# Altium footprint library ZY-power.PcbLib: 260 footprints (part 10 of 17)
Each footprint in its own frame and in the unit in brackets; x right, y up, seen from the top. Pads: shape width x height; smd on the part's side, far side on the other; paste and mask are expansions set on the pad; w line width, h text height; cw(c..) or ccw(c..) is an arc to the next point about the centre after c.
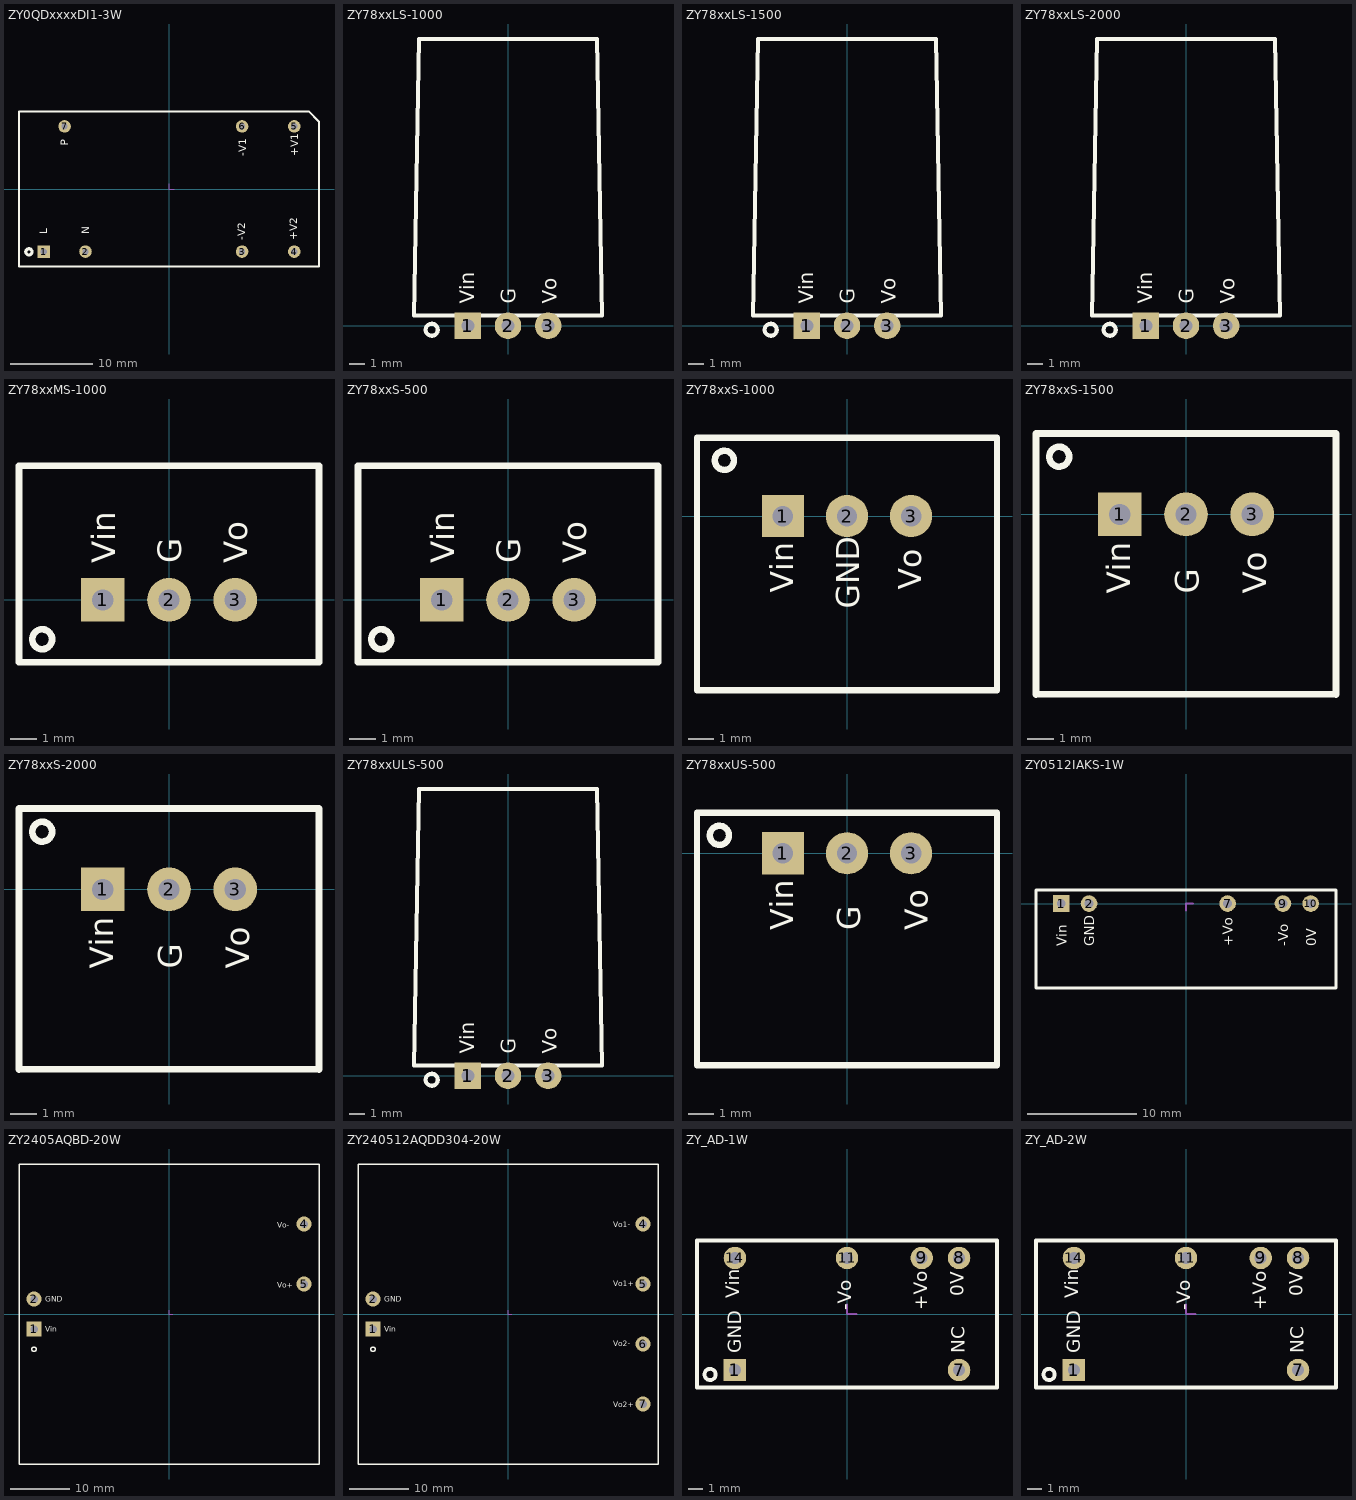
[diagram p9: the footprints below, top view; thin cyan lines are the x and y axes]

## ZY0QDxxxxDI1-3W [mil]
height 677.17
pads (7):
  rect 60x60 hole 30: 1(-600,-300)
  round 60 hole 30: 2(-400,-300) 3(350,-300) 4(600,-300) 5(600,300) 6(350,300) 7(-500,300)
Top Overlay:
  circle w15: c-671,-301 r15
  lines w10: -718.5,-372.05 718.5,-372.05 718.5,322.05 668.5,372.05 -718.5,372.05 -718.5,-372.05
  text "-V1" at 370,158 h36
  text "+V1" at 618,158 h36
  text "+V2" at 614,-245 h36
  text "-V2" at 366,-245 h36
  text "N" at -382,-216 h36
  text "L" at -583,-216 h36
  text "P" at -483,208 h36
Mechanical 15:
  lines w5: 0,25 0,0 25,0

## ZY78xxLS-1000 [mil]
height 393.7
pads (3):
  rect 66x66 hole 32: 1(-100,0)
  round 66 hole 32: 2(0,0) 3(100,0)
Top Overlay:
  circle w10: c-190,-10 r15
  lines w10: -234.25,25.35 -222.24,714.32 222.24,714.32 234.25,25.35 -234.25,25.35
  text "Vin" at -84,55 h36
  text "G" at 19,55 h36
  text "Vo" at 121,55 h36

## ZY78xxLS-1500 [mil]
height 393.7
pads (3):
  rect 66x66 hole 32: 1(-100,0)
  round 66 hole 32: 2(0,0) 3(100,0)
Top Overlay:
  circle w10: c-190,-10 r15
  lines w10: -234.25,25.35 -222.24,714.32 222.24,714.32 234.25,25.35 -234.25,25.35
  text "Vin" at -84,55 h36
  text "G" at 19,55 h36
  text "Vo" at 121,55 h36

## ZY78xxLS-2000 [mil]
height 393.7
pads (3):
  rect 66x66 hole 32: 1(-100,0)
  round 66 hole 32: 2(0,0) 3(100,0)
Top Overlay:
  circle w10: c-190,-10 r15
  lines w10: -234.25,25.35 -222.24,714.32 222.24,714.32 234.25,25.35 -234.25,25.35
  text "Vin" at -84,55 h36
  text "G" at 19,55 h36
  text "Vo" at 121,55 h36

## ZY78xxMS-1000 [mil]
height 401.57
pads (3):
  rect 66x66 hole 32: 1(-100,0)
  round 66 hole 32: 2(0,0) 3(100,0)
Top Overlay:
  circle w10: c-191.5,-59.49 r15
  lines w10: -226.5,-94.49 -226.5,202.76 226.5,202.76 226.5,-94.49 -226.5,-94.49
  text "Vin" at -81.5,55 h36
  text "G" at 18.5,55 h36
  text "Vo" at 118.5,55 h36

## ZY78xxS-500 [mil]
pads (3):
  rect 66x66 hole 32: 1(-100,0)
  round 66 hole 32: 2(0,0) 3(100,0)
Top Overlay:
  circle w10: c-191.5,-59.49 r15
  lines w10: -226.5,-94.49 -226.5,202.76 226.5,202.76 226.5,-94.49 -226.5,-94.49
  text "Vin" at -81.5,55 h36
  text "G" at 18.5,55 h36
  text "Vo" at 118.5,55 h36

## ZY78xxS-1000 [mil]
height 688.98
pads (3):
  rect 66x66 hole 32: 1(-100,0)
  round 66 hole 32: 2(0,0) 3(100,0)
Top Overlay:
  circle w10: c-191.5,87.05 r15
  lines w10: -234.25,-271.65 -234.25,122.05 234.25,122.05 234.25,-271.65 -234.25,-271.65
  text "Vin" at -84,-120 h36
  text "GND" at 19,-145 h36
  text "Vo" at 116,-115 h36

## ZY78xxS-1500 [mil]
height 688.98
pads (3):
  rect 66x66 hole 32: 1(-100,0)
  round 66 hole 32: 2(0,0) 3(100,0)
Top Overlay:
  circle w10: c-191.5,87.05 r15
  lines w10: -226.5,-271.95 -226.5,122.05 226.5,122.05 226.5,-271.95 ; -226.5,-271.65 226.5,-271.65
  text "Vin" at -84,-120 h36
  text "G" at 19,-120 h36
  text "Vo" at 121,-120 h36

## ZY78xxS-2000 [mil]
height 688.98
pads (3):
  rect 66x66 hole 32: 1(-100,0)
  round 66 hole 32: 2(0,0) 3(100,0)
Top Overlay:
  circle w10: c-191.5,87.05 r15
  lines w10: -226.5,-271.95 -226.5,122.05 226.5,122.05 226.5,-271.95 ; -226.5,-271.65 226.5,-271.65
  text "Vin" at -84,-120 h36
  text "G" at 19,-120 h36
  text "Vo" at 121,-120 h36

## ZY78xxULS-500 [mil]
height 393.7
pads (3):
  rect 66x66 hole 32: 1(-100,0)
  round 66 hole 32: 2(0,0) 3(100,0)
Top Overlay:
  circle w10: c-190,-10 r15
  lines w10: -234.25,25.35 -222.24,714.32 222.24,714.32 234.25,25.35 -234.25,25.35
  text "Vin" at -84,55 h36
  text "G" at 19,55 h36
  text "Vo" at 121,55 h36

## ZY78xxUS-500 [mil]
height 688.98
pads (3):
  rect 66x66 hole 32: 1(-100,0)
  round 66 hole 32: 2(0,0) 3(100,0)
Top Overlay:
  circle w10: c-199.25,27.99 r15
  lines w10: -234.25,-330.71 234.25,-330.71 234.25,62.99 -234.25,62.99 -234.25,-330.71
  text "Vo" at 126,-120 h36
  text "G" at 21,-120 h36
  text "Vin" at -84,-120 h36

## ZY0512IAKS-1W [mil]
pads (5):
  rect 60x60 hole 32: 1(-450,0)
  round 60 hole 32: 2(-350,0) 7(150,0) 9(350,0) 10(450,0)
Top Overlay:
  lines w10: -541.34,-305.12 541.34,-305.12 541.34,49.21 -541.34,49.21 -541.34,-305.12
  text "Vin" at -430.5,-155 h36
  text "GND" at -330.5,-155 h36
  text "+Vo" at 169.5,-155 h36
  text "-Vo" at 369.5,-155 h36
  text "0V" at 469.5,-155 h36
Mechanical 15:
  lines w8: 0,-25 0,0 25,0

## ZY2405AQBD-20W [mil]
pads (4):
  rect 100x100 hole 50: 1(-900,-100)
  round 100 hole 50: 2(-900,100) 4(900,600) 5(900,200)
Top Overlay:
  circle w10: c-900,-235 r15
  lines w10: -1000,-1000 -1000,1000 1000,1000 1000,-1000 -1000,-1000
  text "GND" at -825,80.08 h36
  text "Vin" at -825,-119.92 h36
  text "Vo-" at 720,575.08 h36
  text "Vo+" at 720,175.08 h36
Mechanical 15:
  lines w5: 0,25 0,0 25,0

## ZY240512AQDD304-20W [mil]
pads (6):
  rect 100x100 hole 50: 1(-900,-100)
  round 100 hole 50: 2(-900,100) 4(900,600) 5(900,200) 6(900,-200) 7(900,-600)
Top Overlay:
  circle w10: c-900,-235 r15
  lines w10: -1000,-1000 1000,-1000 1000,1000 -1000,1000 -1000,-1000
  text "Vo1-" at 700,580 h36
  text "Vo2-" at 700,-215 h36
  text "Vo2+" at 700,-620 h36
  text "Vo1+" at 700,185 h36
  text "Vin" at -825,-119.92 h36
  text "GND" at -825,80.08 h36
Mechanical 15:
  lines w5: 0,25 0,0 25,0

## ZY_AD-1W [mil]
height 318.9
pads (6):
  rect 60x60 hole 32: 1(-300,-150)
  round 60 hole 32: 7(300,-150) 8(300,150) 9(200,150) 11(0,150) 14(-300,150)
Top Overlay:
  circle w10: c-366.57,-161.85 r15
  lines w10: -401.57,-196.85 -401.57,196.85 401.57,196.85 401.57,-196.85 -401.57,-196.85
  text "GND" at -283,-105 h36
  text "NC" at 315,-105 h36
  text "Vin" at -288,42.37 h36
  text "-Vo" at 12,10.66 h36
  text "+Vo" at 215,10.66 h36
  text "0V" at 312,47 h36
Mechanical 15:
  lines w5: 0,25 0,0 25,0

## ZY_AD-2W [mil]
height 318.9
pads (6):
  rect 60x60 hole 32: 1(-300,-150)
  round 60 hole 32: 7(300,-150) 8(300,150) 9(200,150) 11(0,150) 14(-300,150)
Top Overlay:
  circle w10: c-366.57,-161.85 r15
  lines w10: -401.57,-196.85 401.57,-196.85 401.57,196.85 -401.57,196.85 -401.57,-196.85
  text "0V" at 312,47 h36
  text "+Vo" at 215,10.66 h36
  text "-Vo" at 12,10.66 h36
  text "Vin" at -288,42.37 h36
  text "NC" at 315,-105 h36
  text "GND" at -283,-105 h36
Mechanical 15:
  lines w5: 0,25 0,0 25,0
